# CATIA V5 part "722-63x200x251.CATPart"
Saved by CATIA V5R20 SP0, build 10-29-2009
Part number: 722-63x200x251
Definition: NONE
Nomenclature: 722-63x200x251
Source: Unknown
Description: 722-63x200x251
Bounding box of the stored display mesh (mm): x -31.5 to 31.5, y -31.5 to 31.5, z -182 to 69
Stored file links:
  C:\Users\Utente\Desktop\IO LAVORO\3D X SITO CF\X SITO\722\722-63x200x251.CATPart
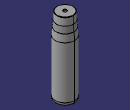
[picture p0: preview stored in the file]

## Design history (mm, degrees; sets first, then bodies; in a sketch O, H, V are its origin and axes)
Body1 "722-63x200x251" (main body)
  Solid1: solid without history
